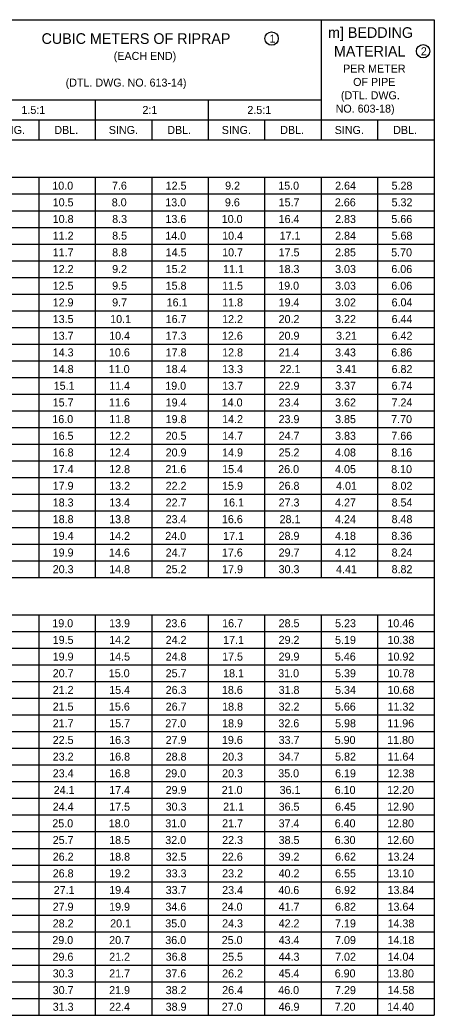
# Model space of a CAD drawing. Extents: x 49991.4 to 50047.6, y 49987.6 to 50011.4.
# Drawn here: x 50036.73 to 50039.83, y 50003.6 to 50011.06 of the extents above; entities that cross this region are included whole.
import ezdxf

# ---------------------------------------------------------------- set-up
doc = ezdxf.new("R2010")
doc.units = 0
doc.layers.add('Level 5', color=7, linetype='Continuous')

msp = doc.modelspace()

# ---------------------------------------------------------------- linework, layer by layer
at = {"layer": 'Level 5'}
for p, q in [((50031.9605, 50011.0583), (50039.8305, 50011.0583)), ((50038.9843, 50011.0583), (50038.9843, 50010.1583)), ((50039.8305, 50011.0583), (50039.8305, 50003.5983)), ((50033.9071, 50010.4583), (50038.9843, 50010.4583)), ((50037.2919, 50010.4583), (50037.2919, 50010.1583)), ((50038.1381, 50010.4583), (50038.1381, 50010.1583)), ((50031.9605, 50010.3083), (50039.8305, 50010.3083)), ((50036.8688, 50010.3083), (50036.8688, 50010.1583)), ((50037.715, 50010.3083), (50037.715, 50010.1583)), ((50038.5612, 50010.3083), (50038.5612, 50010.1583)), ((50039.4074, 50010.3083), (50039.4074, 50010.1583)), ((50031.9605, 50010.1583), (50039.8305, 50010.1583)), ((50031.9605, 50009.8783), (50039.8305, 50009.8783)), ((50036.8688, 50009.8783), (50036.8688, 50006.8783)), ((50037.2919, 50009.8783), (50037.2919, 50006.8783)), ((50037.715, 50009.8783), (50037.715, 50006.8783)), ((50038.1381, 50009.8783), (50038.1381, 50006.8783)), ((50038.5612, 50009.8783), (50038.5612, 50006.8783)), ((50038.9843, 50009.8783), (50038.9843, 50006.8783)), ((50039.4074, 50009.8783), (50039.4074, 50006.8783)), ((50031.9605, 50009.7533), (50039.8305, 50009.7533)), ((50031.9605, 50009.6283), (50039.8305, 50009.6283)), ((50031.9605, 50009.5033), (50039.8305, 50009.5033)), ((50031.9605, 50009.3783), (50039.8305, 50009.3783)), ((50031.9605, 50009.2533), (50039.8305, 50009.2533)), ((50031.9605, 50009.1283), (50039.8305, 50009.1283)), ((50031.9605, 50009.0033), (50039.8305, 50009.0033)), ((50031.9605, 50008.8783), (50039.8305, 50008.8783)), ((50031.9605, 50008.7533), (50039.8305, 50008.7533)), ((50031.9605, 50008.6283), (50039.8305, 50008.6283)), ((50031.9605, 50008.5033), (50039.8305, 50008.5033)), ((50031.9605, 50008.3783), (50039.8305, 50008.3783)), ((50031.9605, 50008.2533), (50039.8305, 50008.2533)), ((50031.9605, 50008.1283), (50039.8305, 50008.1283)), ((50031.9605, 50008.0033), (50039.8305, 50008.0033)), ((50031.9605, 50007.8783), (50039.8305, 50007.8783)), ((50031.9605, 50007.7533), (50039.8305, 50007.7533)), ((50031.9605, 50007.6283), (50039.8305, 50007.6283)), ((50031.9605, 50007.5033), (50039.8305, 50007.5033)), ((50031.9605, 50007.3783), (50039.8305, 50007.3783)), ((50031.9605, 50007.2533), (50039.8305, 50007.2533)), ((50031.9605, 50007.1283), (50039.8305, 50007.1283)), ((50031.9605, 50007.0033), (50039.8305, 50007.0033)), ((50031.9605, 50006.8783), (50039.8305, 50006.8783)), ((50031.9605, 50006.5983), (50039.8305, 50006.5983)), ((50036.8688, 50006.5983), (50036.8688, 50003.5983)), ((50037.2919, 50006.5983), (50037.2919, 50003.5983)), ((50037.715, 50006.5983), (50037.715, 50003.5983)), ((50038.1381, 50006.5983), (50038.1381, 50003.5983)), ((50038.5612, 50006.5983), (50038.5612, 50003.5983)), ((50038.9843, 50006.5983), (50038.9843, 50003.5983)), ((50039.4074, 50006.5983), (50039.4074, 50003.5983)), ((50031.9605, 50006.4733), (50039.8305, 50006.4733)), ((50031.9605, 50006.3483), (50039.8305, 50006.3483)), ((50031.9605, 50006.2233), (50039.8305, 50006.2233)), ((50031.9605, 50006.0983), (50039.8305, 50006.0983)), ((50031.9605, 50005.9733), (50039.8305, 50005.9733)), ((50031.9605, 50005.8483), (50039.8305, 50005.8483)), ((50031.9605, 50005.7233), (50039.8305, 50005.7233)), ((50031.9605, 50005.5983), (50039.8305, 50005.5983)), ((50031.9605, 50005.4733), (50039.8305, 50005.4733)), ((50031.9605, 50005.3483), (50039.8305, 50005.3483)), ((50031.9605, 50005.2233), (50039.8305, 50005.2233)), ((50031.9605, 50005.0983), (50039.8305, 50005.0983)), ((50031.9605, 50004.9733), (50039.8305, 50004.9733)), ((50031.9605, 50004.8483), (50039.8305, 50004.8483)), ((50031.9605, 50004.7233), (50039.8305, 50004.7233)), ((50031.9605, 50004.5983), (50039.8305, 50004.5983)), ((50031.9605, 50004.4733), (50039.8305, 50004.4733)), ((50031.9605, 50004.3483), (50039.8305, 50004.3483)), ((50031.9605, 50004.2233), (50039.8305, 50004.2233)), ((50031.9605, 50004.0983), (50039.8305, 50004.0983)), ((50031.9605, 50003.9733), (50039.8305, 50003.9733)), ((50031.9605, 50003.8483), (50039.8305, 50003.8483)), ((50031.9605, 50003.7233), (50039.8305, 50003.7233)), ((50031.9605, 50003.5983), (50039.8305, 50003.5983))]:
    msp.add_line(p, q, dxfattribs=at)
for centre in [(50038.6135, 50010.9183), (50039.7484, 50010.8233)]:
    msp.add_circle(centre, 0.05, dxfattribs=at)

# ---------------------------------------------------------------- texts
for s, height, p in [('CUBIC METERS OF RIPRAP', 0.08, (50036.8898, 50010.8783)), ('1', 0.06, (50038.5976, 50010.8883)), ('m] BEDDING', 0.08, (50039.0364, 50010.9233)), ('(EACH END)', 0.06, (50037.4305, 50010.7583)), ('MATERIAL ', 0.08, (50039.0805, 50010.7833)), ('2', 0.06, (50039.7314, 50010.7933)), ('PER METER', 0.06, (50039.1488, 50010.6633)), ('(DTL. DWG. NO. 613-14)', 0.06, (50037.0705, 50010.5583)), ('OF PIPE', 0.06, (50039.224, 50010.5633)), ('(DTL. DWG.', 0.06, (50039.1326, 50010.4633)), ('NO. 603-18)', 0.06, (50039.093, 50010.3633)), ('1.5:1', 0.06, (50036.7392, 50010.3533)), ('2:1', 0.06, (50037.6454, 50010.3533)), ('2.5:1', 0.06, (50038.4316, 50010.3533)), ('SING.', 0.06, (50036.5473, 50010.2033)), ('DBL.', 0.06, (50036.9856, 50010.2033)), ('SING.', 0.06, (50037.3935, 50010.2033)), ('DBL.', 0.06, (50037.8318, 50010.2033)), ('SING.', 0.06, (50038.2397, 50010.2033)), ('DBL.', 0.06, (50038.678, 50010.2033)), ('SING.', 0.06, (50039.0859, 50010.2033)), ('DBL.', 0.06, (50039.5242, 50010.2033)), ('10.0', 0.06, (50036.9704, 50009.7858)), (' 7.6', 0.06, (50037.3949, 50009.7858)), ('12.5', 0.06, (50037.8196, 50009.7858)), (' 9.2', 0.06, (50038.2427, 50009.7858)), ('15.0', 0.06, (50038.6628, 50009.7858)), ('2.64', 0.06, (50039.0889, 50009.7858)), ('5.28', 0.06, (50039.512, 50009.7858)), ('10.5', 0.06, (50036.9734, 50009.6608)), (' 8.0', 0.06, (50037.3935, 50009.6608)), ('13.0', 0.06, (50037.8166, 50009.6608)), (' 9.6', 0.06, (50038.2411, 50009.6608)), ('15.7', 0.06, (50038.6658, 50009.6608)), ('2.66', 0.06, (50039.0873, 50009.6608)), ('5.32', 0.06, (50039.512, 50009.6608)), ('10.8', 0.06, (50036.9734, 50009.5358)), (' 8.3', 0.06, (50037.3965, 50009.5358)), ('13.6', 0.06, (50037.818, 50009.5358)), ('10.0', 0.06, (50038.2397, 50009.5358)), ('16.4', 0.06, (50038.6658, 50009.5358)), ('2.83', 0.06, (50039.0889, 50009.5358)), ('5.66', 0.06, (50039.5104, 50009.5358)), ('11.2', 0.06, (50036.9734, 50009.4108)), (' 8.5', 0.06, (50037.3965, 50009.4108)), ('14.0', 0.06, (50037.8166, 50009.4108)), ('10.4', 0.06, (50038.2427, 50009.4108)), ('17.1', 0.06, (50038.6732, 50009.4108)), ('2.84', 0.06, (50039.0889, 50009.4108)), ('5.68', 0.06, (50039.512, 50009.4108)), ('11.7', 0.06, (50036.9734, 50009.2858)), (' 8.8', 0.06, (50037.3965, 50009.2858)), ('14.5', 0.06, (50037.8196, 50009.2858)), ('10.7', 0.06, (50038.2427, 50009.2858)), ('17.5', 0.06, (50038.6658, 50009.2858)), ('2.85', 0.06, (50039.0889, 50009.2858)), ('5.70', 0.06, (50039.509, 50009.2858)), ('12.2', 0.06, (50036.9734, 50009.1608)), (' 9.2', 0.06, (50037.3965, 50009.1608)), ('15.2', 0.06, (50037.8196, 50009.1608)), ('11.1', 0.06, (50038.2501, 50009.1608)), ('18.3', 0.06, (50038.6658, 50009.1608)), ('3.03', 0.06, (50039.0889, 50009.1608)), ('6.06', 0.06, (50039.5104, 50009.1608)), ('12.5', 0.06, (50036.9734, 50009.0358)), (' 9.5', 0.06, (50037.3965, 50009.0358)), ('15.8', 0.06, (50037.8196, 50009.0358)), ('11.5', 0.06, (50038.2427, 50009.0358)), ('19.0', 0.06, (50038.6628, 50009.0358)), ('3.03', 0.06, (50039.0889, 50009.0358)), ('6.06', 0.06, (50039.5104, 50009.0358)), ('12.9', 0.06, (50036.9732, 50008.9108)), (' 9.7', 0.06, (50037.3965, 50008.9108)), ('16.1', 0.06, (50037.827, 50008.9108)), ('11.8', 0.06, (50038.2427, 50008.9108)), ('19.4', 0.06, (50038.6658, 50008.9108)), ('3.02', 0.06, (50039.0889, 50008.9108)), ('6.04', 0.06, (50039.512, 50008.9108)), ('13.5', 0.06, (50036.9734, 50008.7858)), ('10.1', 0.06, (50037.4039, 50008.7858)), ('16.7', 0.06, (50037.8196, 50008.7858)), ('12.2', 0.06, (50038.2427, 50008.7858)), ('20.2', 0.06, (50038.6658, 50008.7858)), ('3.22', 0.06, (50039.0889, 50008.7858)), ('6.44', 0.06, (50039.512, 50008.7858)), ('13.7', 0.06, (50036.9734, 50008.6608)), ('10.4', 0.06, (50037.3965, 50008.6608)), ('17.3', 0.06, (50037.8196, 50008.6608)), ('12.6', 0.06, (50038.2411, 50008.6608)), ('20.9', 0.06, (50038.6656, 50008.6608)), ('3.21', 0.06, (50039.0963, 50008.6608)), ('6.42', 0.06, (50039.512, 50008.6608)), ('14.3', 0.06, (50036.9734, 50008.5358)), ('10.6', 0.06, (50037.3949, 50008.5358)), ('17.8', 0.06, (50037.8196, 50008.5358)), ('12.8', 0.06, (50038.2427, 50008.5358)), ('21.4', 0.06, (50038.6658, 50008.5358)), ('3.43', 0.06, (50039.0889, 50008.5358)), ('6.86', 0.06, (50039.5104, 50008.5358)), ('14.8', 0.06, (50036.9734, 50008.4108)), ('11.0', 0.06, (50037.3935, 50008.4108)), ('18.4', 0.06, (50037.8196, 50008.4108)), ('13.3', 0.06, (50038.2427, 50008.4108)), ('22.1', 0.06, (50038.6732, 50008.4108)), ('3.41', 0.06, (50039.0963, 50008.4108)), ('6.82', 0.06, (50039.512, 50008.4108)), ('15.1', 0.06, (50036.9808, 50008.2858)), ('11.4', 0.06, (50037.3965, 50008.2858)), ('19.0', 0.06, (50037.8166, 50008.2858)), ('13.7', 0.06, (50038.2427, 50008.2858)), ('22.9', 0.06, (50038.6656, 50008.2858)), ('3.37', 0.06, (50039.0889, 50008.2858)), ('6.74', 0.06, (50039.512, 50008.2858)), ('15.7', 0.06, (50036.9734, 50008.1608)), ('11.6', 0.06, (50037.3949, 50008.1608)), ('19.4', 0.06, (50037.8196, 50008.1608)), ('14.0', 0.06, (50038.2397, 50008.1608)), ('23.4', 0.06, (50038.6658, 50008.1608)), ('3.62', 0.06, (50039.0889, 50008.1608)), ('7.24', 0.06, (50039.512, 50008.1608)), ('16.0', 0.06, (50036.9704, 50008.0358)), ('11.8', 0.06, (50037.3965, 50008.0358)), ('19.8', 0.06, (50037.8196, 50008.0358)), ('14.2', 0.06, (50038.2427, 50008.0358)), ('23.9', 0.06, (50038.6656, 50008.0358)), ('3.85', 0.06, (50039.0889, 50008.0358)), ('7.70', 0.06, (50039.509, 50008.0358)), ('16.5', 0.06, (50036.9734, 50007.9108)), ('12.2', 0.06, (50037.3965, 50007.9108)), ('20.5', 0.06, (50037.8196, 50007.9108)), ('14.7', 0.06, (50038.2427, 50007.9108)), ('24.7', 0.06, (50038.6658, 50007.9108)), ('3.83', 0.06, (50039.0889, 50007.9108)), ('7.66', 0.06, (50039.5104, 50007.9108)), ('16.8', 0.06, (50036.9734, 50007.7858)), ('12.4', 0.06, (50037.3965, 50007.7858)), ('20.9', 0.06, (50037.8194, 50007.7858)), ('14.9', 0.06, (50038.2425, 50007.7858)), ('25.2', 0.06, (50038.6658, 50007.7858)), ('4.08', 0.06, (50039.0889, 50007.7858)), ('8.16', 0.06, (50039.5104, 50007.7858)), ('17.4', 0.06, (50036.9734, 50007.6608)), ('12.8', 0.06, (50037.3965, 50007.6608)), ('21.6', 0.06, (50037.818, 50007.6608)), ('15.4', 0.06, (50038.2427, 50007.6608)), ('26.0', 0.06, (50038.6628, 50007.6608)), ('4.05', 0.06, (50039.0889, 50007.6608)), ('8.10', 0.06, (50039.509, 50007.6608)), ('17.9', 0.06, (50036.9732, 50007.5358)), ('13.2', 0.06, (50037.3965, 50007.5358)), ('22.2', 0.06, (50037.8196, 50007.5358)), ('15.9', 0.06, (50038.2425, 50007.5358)), ('26.8', 0.06, (50038.6658, 50007.5358)), ('4.01', 0.06, (50039.0963, 50007.5358)), ('8.02', 0.06, (50039.512, 50007.5358)), ('18.3', 0.06, (50036.9734, 50007.4108)), ('13.4', 0.06, (50037.3965, 50007.4108)), ('22.7', 0.06, (50037.8196, 50007.4108)), ('16.1', 0.06, (50038.2501, 50007.4108)), ('27.3', 0.06, (50038.6658, 50007.4108)), ('4.27', 0.06, (50039.0889, 50007.4108)), ('8.54', 0.06, (50039.512, 50007.4108)), ('18.8', 0.06, (50036.9734, 50007.2858)), ('13.8', 0.06, (50037.3965, 50007.2858)), ('23.4', 0.06, (50037.8196, 50007.2858)), ('16.6', 0.06, (50038.2411, 50007.2858)), ('28.1', 0.06, (50038.6732, 50007.2858)), ('4.24', 0.06, (50039.0889, 50007.2858)), ('8.48', 0.06, (50039.512, 50007.2858)), ('19.4', 0.06, (50036.9734, 50007.1608)), ('14.2', 0.06, (50037.3965, 50007.1608)), ('24.0', 0.06, (50037.8166, 50007.1608)), ('17.1', 0.06, (50038.2501, 50007.1608)), ('28.9', 0.06, (50038.6656, 50007.1608)), ('4.18', 0.06, (50039.0889, 50007.1608)), ('8.36', 0.06, (50039.5104, 50007.1608)), ('19.9', 0.06, (50036.9732, 50007.0358)), ('14.6', 0.06, (50037.3949, 50007.0358)), ('24.7', 0.06, (50037.8196, 50007.0358)), ('17.6', 0.06, (50038.2411, 50007.0358)), ('29.7', 0.06, (50038.6658, 50007.0358)), ('4.12', 0.06, (50039.0889, 50007.0358)), ('8.24', 0.06, (50039.512, 50007.0358)), ('20.3', 0.06, (50036.9734, 50006.9108)), ('14.8', 0.06, (50037.3965, 50006.9108)), ('25.2', 0.06, (50037.8196, 50006.9108)), ('17.9', 0.06, (50038.2425, 50006.9108)), ('30.3', 0.06, (50038.6658, 50006.9108)), ('4.41', 0.06, (50039.0963, 50006.9108)), ('8.82', 0.06, (50039.512, 50006.9108)), ('19.0', 0.06, (50036.9704, 50006.5058)), ('13.9', 0.06, (50037.3963, 50006.5058)), ('23.6', 0.06, (50037.818, 50006.5058)), ('16.7', 0.06, (50038.2427, 50006.5058)), ('28.5', 0.06, (50038.6658, 50006.5058)), ('5.23', 0.06, (50039.0889, 50006.5058)), ('10.46', 0.06, (50039.4804, 50006.5058)), ('19.5', 0.06, (50036.9734, 50006.3808)), ('14.2', 0.06, (50037.3965, 50006.3808)), ('24.2', 0.06, (50037.8196, 50006.3808)), ('17.1', 0.06, (50038.2501, 50006.3808)), ('29.2', 0.06, (50038.6658, 50006.3808)), ('5.19', 0.06, (50039.0887, 50006.3808)), ('10.38', 0.06, (50039.482, 50006.3808)), ('19.9', 0.06, (50036.9732, 50006.2558)), ('14.5', 0.06, (50037.3965, 50006.2558)), ('24.8', 0.06, (50037.8196, 50006.2558)), ('17.5', 0.06, (50038.2427, 50006.2558)), ('29.9', 0.06, (50038.6656, 50006.2558)), ('5.46', 0.06, (50039.0873, 50006.2558)), ('10.92', 0.06, (50039.482, 50006.2558)), ('20.7', 0.06, (50036.9734, 50006.1308)), ('15.0', 0.06, (50037.3935, 50006.1308)), ('25.7', 0.06, (50037.8196, 50006.1308)), ('18.1', 0.06, (50038.2501, 50006.1308)), ('31.0', 0.06, (50038.6628, 50006.1308)), ('5.39', 0.06, (50039.0887, 50006.1308)), ('10.78', 0.06, (50039.482, 50006.1308)), ('21.2', 0.06, (50036.9734, 50006.0058)), ('15.4', 0.06, (50037.3965, 50006.0058)), ('26.3', 0.06, (50037.8196, 50006.0058)), ('18.6', 0.06, (50038.2411, 50006.0058)), ('31.8', 0.06, (50038.6658, 50006.0058)), ('5.34', 0.06, (50039.0889, 50006.0058)), ('10.68', 0.06, (50039.482, 50006.0058)), ('21.5', 0.06, (50036.9734, 50005.8808)), ('15.6', 0.06, (50037.3949, 50005.8808)), ('26.7', 0.06, (50037.8196, 50005.8808)), ('18.8', 0.06, (50038.2427, 50005.8808)), ('32.2', 0.06, (50038.6658, 50005.8808)), ('5.66', 0.06, (50039.0873, 50005.8808)), ('11.32', 0.06, (50039.482, 50005.8808)), ('21.7', 0.06, (50036.9734, 50005.7558)), ('15.7', 0.06, (50037.3965, 50005.7558)), ('27.0', 0.06, (50037.8166, 50005.7558)), ('18.9', 0.06, (50038.2425, 50005.7558)), ('32.6', 0.06, (50038.6642, 50005.7558)), ('5.98', 0.06, (50039.0889, 50005.7558)), ('11.96', 0.06, (50039.4804, 50005.7558)), ('22.5', 0.06, (50036.9734, 50005.6308)), ('16.3', 0.06, (50037.3965, 50005.6308)), ('27.9', 0.06, (50037.8194, 50005.6308)), ('19.6', 0.06, (50038.2411, 50005.6308)), ('33.7', 0.06, (50038.6658, 50005.6308)), ('5.90', 0.06, (50039.0859, 50005.6308)), ('11.80', 0.06, (50039.479, 50005.6308)), ('23.2', 0.06, (50036.9734, 50005.5058)), ('16.8', 0.06, (50037.3965, 50005.5058)), ('28.8', 0.06, (50037.8196, 50005.5058)), ('20.3', 0.06, (50038.2427, 50005.5058)), ('34.7', 0.06, (50038.6658, 50005.5058)), ('5.82', 0.06, (50039.0889, 50005.5058)), ('11.64', 0.06, (50039.482, 50005.5058)), ('23.4', 0.06, (50036.9734, 50005.3808)), ('16.8', 0.06, (50037.3965, 50005.3808)), ('29.0', 0.06, (50037.8166, 50005.3808)), ('20.3', 0.06, (50038.2427, 50005.3808)), ('35.0', 0.06, (50038.6628, 50005.3808)), ('6.19', 0.06, (50039.0887, 50005.3808)), ('12.38', 0.06, (50039.482, 50005.3808)), ('24.1', 0.06, (50036.9808, 50005.2558)), ('17.4', 0.06, (50037.3965, 50005.2558)), ('29.9', 0.06, (50037.8194, 50005.2558)), ('21.0', 0.06, (50038.2397, 50005.2558)), ('36.1', 0.06, (50038.6732, 50005.2558)), ('6.10', 0.06, (50039.0859, 50005.2558)), ('12.20', 0.06, (50039.479, 50005.2558)), ('24.4', 0.06, (50036.9734, 50005.1308)), ('17.5', 0.06, (50037.3965, 50005.1308)), ('30.3', 0.06, (50037.8196, 50005.1308)), ('21.1', 0.06, (50038.2501, 50005.1308)), ('36.5', 0.06, (50038.6658, 50005.1308)), ('6.45', 0.06, (50039.0889, 50005.1308)), ('12.90', 0.06, (50039.479, 50005.1308)), ('25.0', 0.06, (50036.9704, 50005.0058)), ('18.0', 0.06, (50037.3935, 50005.0058)), ('31.0', 0.06, (50037.8166, 50005.0058)), ('21.7', 0.06, (50038.2427, 50005.0058)), ('37.4', 0.06, (50038.6658, 50005.0058)), ('6.40', 0.06, (50039.0859, 50005.0058)), ('12.80', 0.06, (50039.479, 50005.0058)), ('25.7', 0.06, (50036.9734, 50004.8808)), ('18.5', 0.06, (50037.3965, 50004.8808)), ('32.0', 0.06, (50037.8166, 50004.8808)), ('22.3', 0.06, (50038.2427, 50004.8808)), ('38.5', 0.06, (50038.6658, 50004.8808)), ('6.30', 0.06, (50039.0859, 50004.8808)), ('12.60', 0.06, (50039.479, 50004.8808)), ('26.2', 0.06, (50036.9734, 50004.7558)), ('18.8', 0.06, (50037.3965, 50004.7558)), ('32.5', 0.06, (50037.8196, 50004.7558)), ('22.6', 0.06, (50038.2411, 50004.7558)), ('39.2', 0.06, (50038.6658, 50004.7558)), ('6.62', 0.06, (50039.0889, 50004.7558)), ('13.24', 0.06, (50039.482, 50004.7558)), ('26.8', 0.06, (50036.9734, 50004.6308)), ('19.2', 0.06, (50037.3965, 50004.6308)), ('33.3', 0.06, (50037.8196, 50004.6308)), ('23.2', 0.06, (50038.2427, 50004.6308)), ('40.2', 0.06, (50038.6658, 50004.6308)), ('6.55', 0.06, (50039.0889, 50004.6308)), ('13.10', 0.06, (50039.479, 50004.6308)), ('27.1', 0.06, (50036.9808, 50004.5058)), ('19.4', 0.06, (50037.3965, 50004.5058)), ('33.7', 0.06, (50037.8196, 50004.5058)), ('23.4', 0.06, (50038.2427, 50004.5058)), ('40.6', 0.06, (50038.6642, 50004.5058)), ('6.92', 0.06, (50039.0889, 50004.5058)), ('13.84', 0.06, (50039.482, 50004.5058)), ('27.9', 0.06, (50036.9732, 50004.3808)), ('19.9', 0.06, (50037.3963, 50004.3808)), ('34.6', 0.06, (50037.818, 50004.3808)), ('24.0', 0.06, (50038.2397, 50004.3808)), ('41.7', 0.06, (50038.6658, 50004.3808)), ('6.82', 0.06, (50039.0889, 50004.3808)), ('13.64', 0.06, (50039.482, 50004.3808)), ('28.2', 0.06, (50036.9734, 50004.2558)), ('20.1', 0.06, (50037.4039, 50004.2558)), ('35.0', 0.06, (50037.8166, 50004.2558)), ('24.3', 0.06, (50038.2427, 50004.2558)), ('42.2', 0.06, (50038.6658, 50004.2558)), ('7.19', 0.06, (50039.0887, 50004.2558)), ('14.38', 0.06, (50039.482, 50004.2558)), ('29.0', 0.06, (50036.9704, 50004.1308)), ('20.7', 0.06, (50037.3965, 50004.1308)), ('36.0', 0.06, (50037.8166, 50004.1308)), ('25.0', 0.06, (50038.2397, 50004.1308)), ('43.4', 0.06, (50038.6658, 50004.1308)), ('7.09', 0.06, (50039.0887, 50004.1308)), ('14.18', 0.06, (50039.482, 50004.1308)), ('29.6', 0.06, (50036.9718, 50004.0058)), ('21.2', 0.06, (50037.3965, 50004.0058)), ('36.8', 0.06, (50037.8196, 50004.0058)), ('25.5', 0.06, (50038.2427, 50004.0058)), ('44.3', 0.06, (50038.6658, 50004.0058)), ('7.02', 0.06, (50039.0889, 50004.0058)), ('14.04', 0.06, (50039.482, 50004.0058)), ('30.3', 0.06, (50036.9734, 50003.8808)), ('21.7', 0.06, (50037.3965, 50003.8808)), ('37.6', 0.06, (50037.818, 50003.8808)), ('26.2', 0.06, (50038.2427, 50003.8808)), ('45.4', 0.06, (50038.6658, 50003.8808)), ('6.90', 0.06, (50039.0859, 50003.8808)), ('13.80', 0.06, (50039.479, 50003.8808)), ('30.7', 0.06, (50036.9734, 50003.7558)), ('21.9', 0.06, (50037.3963, 50003.7558)), ('38.2', 0.06, (50037.8196, 50003.7558)), ('26.4', 0.06, (50038.2427, 50003.7558)), ('46.0', 0.06, (50038.6628, 50003.7558)), ('7.29', 0.06, (50039.0887, 50003.7558)), ('14.58', 0.06, (50039.482, 50003.7558)), ('31.3', 0.06, (50036.9734, 50003.6308)), ('22.4', 0.06, (50037.3965, 50003.6308)), ('38.9', 0.06, (50037.8194, 50003.6308)), ('27.0', 0.06, (50038.2397, 50003.6308)), ('46.9', 0.06, (50038.6656, 50003.6308)), ('7.20', 0.06, (50039.0859, 50003.6308)), ('14.40', 0.06, (50039.479, 50003.6308))]:
    msp.add_text(s, height=height, dxfattribs=at).set_placement(p)

doc.saveas('drawing.dxf')
